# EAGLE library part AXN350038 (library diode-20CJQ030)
Matsushita P8 NARROW-PITCH CONNECTORS FOR PC BOARDS 50Pin Socket NARROW-PITCH (0.8mm) CONNECTORS P8 SERIES FEATURES The product lineup consists of the low profile of: - 3 mm - 3.5 mm - 4 mm - 4.5 mm - 5 mm - 5.5 mm - 6 mm - 7 mm - 8 mm - 11.5 mm - 13 mm - 14 mm APPLICATIONS Small portable equipment, laptop computers, video equipment, radio communication, cellular telephones, etc. Please send any comments to: messi@users.sourceforge.net
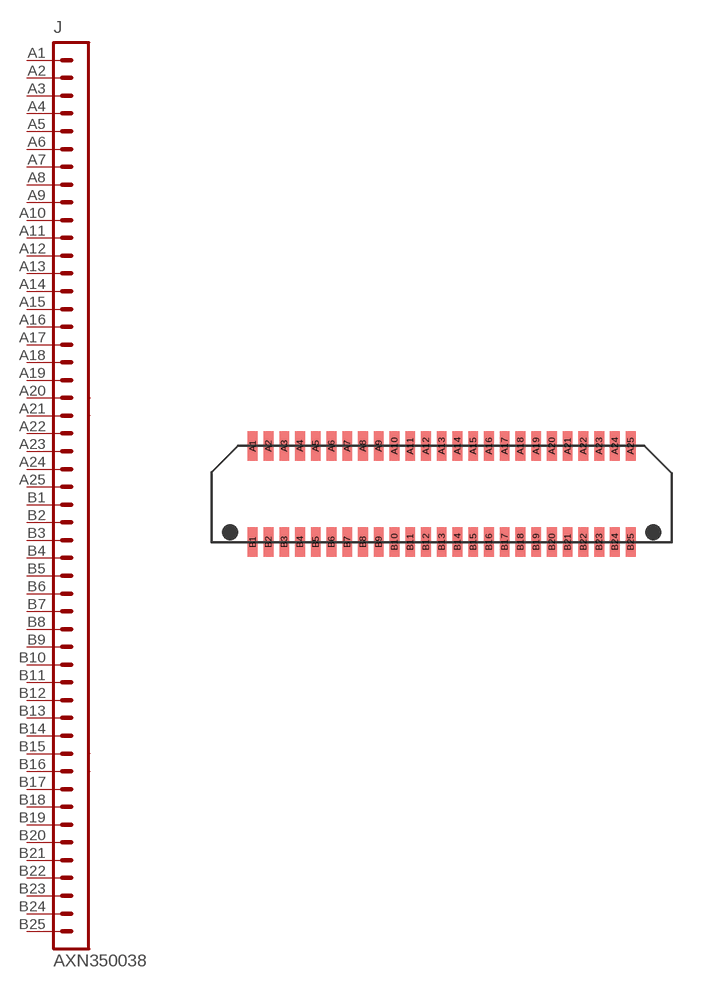
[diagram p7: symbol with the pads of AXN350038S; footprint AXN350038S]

Designator prefix J

## AXN350038  [AXN350038S]
A1  1  pas
A2  2  pas
A3  3  pas
A4  4  pas
A5  5  pas
A6  6  pas
A7  7  pas
A8  8  pas
A9  9  pas
A10  10  pas
A11  11  pas
A12  12  pas
A13  13  pas
A14  14  pas
A15  15  pas
A16  16  pas
A17  17  pas
A18  18  pas
A19  19  pas
A20  20  pas
A21  21  pas
A22  22  pas
A23  23  pas
A24  24  pas
A25  25  pas
B1  26  pas
B2  27  pas
B3  28  pas
B4  29  pas
B5  30  pas
B6  31  pas
B7  32  pas
B8  33  pas
B9  34  pas
B10  35  pas
B11  36  pas
B12  37  pas
B13  38  pas
B14  39  pas
B15  40  pas
B16  41  pas
B17  42  pas
B18  43  pas
B19  44  pas
B20  45  pas
B21  46  pas
B22  47  pas
B23  48  pas
B24  49  pas
B25  50  pas

## Footprint AXN350038S (pad centres in mm)
Matsushita NARROW-PITCH CONNECTORS FOR PC BOARDS 50Pin Socket NARROW-PITCH (0.8mm) CONNECTORS P8 SERIES FEATURES The product lineup consists of the low profile of: - 3 mm - 3.5 mm - 4 mm - 4.5 mm - 5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
smd 0.5 x 1.5: A1 -9.6,2.44; A2 -8.8,2.44; A3 -8,2.44; A4 -7.2,2.44; A5 -6.4,2.44; A6 -5.6,2.44; A7 -4.8,2.44; A8 -4,2.44; A9 -3.2,2.44; A10 -2.4,2.44; A11 -1.6,2.44; A12 -0.8,2.44; A13 0,2.44; A14 0.8,2.44; A15 1.6,2.44; A16 2.4,2.44; A17 3.2,2.44; A18 4,2.44; A19 4.8,2.44; A20 5.6,2.44; A21 6.4,2.44; A22 7.2,2.44; A23 8,2.44; A24 8.8,2.44; A25 9.6,2.44; B1 -9.6,-2.44; B2 -8.8,-2.44; B3 -8,-2.44; B4 -7.2,-2.44; B5 -6.4,-2.44; B6 -5.6,-2.44; B7 -4.8,-2.44; B8 -4,-2.44; B9 -3.2,-2.44; B10 -2.4,-2.44; B11 -1.6,-2.44; B12 -0.8,-2.44; B13 0,-2.44; B14 0.8,-2.44; B15 1.6,-2.44; B16 2.4,-2.44; B17 3.2,-2.44; B18 4,-2.44; B19 4.8,-2.44; B20 5.6,-2.44; B21 6.4,-2.44; B22 7.2,-2.44; B23 8,-2.44; B24 8.8,-2.44; B25 9.6,-2.44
